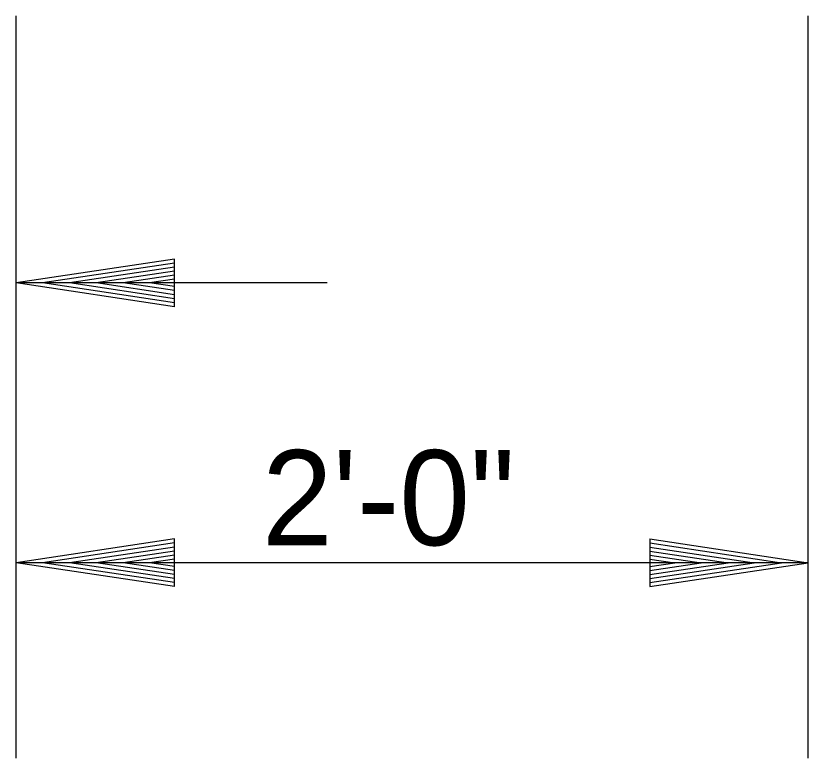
# Model space of a CAD drawing. Extents: x -149 to 1228740, y -106 to 152440.
# Drawn here: x -129.62 to -124.56, y 47.89 to 52.62 of the extents above; entities that cross this region are included whole.
import ezdxf

# ---------------------------------------------------------------- set-up
doc = ezdxf.new("R2010")
doc.units = 0
doc.layers.add('R_Annotation', color=7, linetype='Continuous')
doc.layers.add('R_Dimension', color=7, linetype='Continuous')

msp = doc.modelspace()

# ---------------------------------------------------------------- linework, layer by layer
at = {"layer": 'R_Dimension'}
for p, q in [((-129.6197, 52.6229), (-129.6197, 47.8891)), ((-124.5662, 52.6229), (-124.5662, 47.8891)), ((-128.6075, 51.0711), (-129.6182, 50.9195)), ((-128.6075, 50.7679), (-128.6075, 51.0711)), ((-128.6075, 51.0458), (-129.4489, 50.9195)), ((-128.6075, 51.0205), (-129.2771, 50.9195)), ((-128.6075, 50.9953), (-129.1078, 50.9195)), ((-128.6075, 50.97), (-128.936, 50.9195)), ((-127.6329, 50.9203), (-129.6197, 50.9203)), ((-128.6075, 50.7679), (-129.6182, 50.9195)), ((-128.6075, 50.7931), (-129.4489, 50.9195)), ((-128.6075, 50.8184), (-129.2771, 50.9195)), ((-128.6075, 50.8437), (-129.1078, 50.9195)), ((-128.6075, 50.8715), (-128.936, 50.9195)), ((-128.6075, 50.9447), (-128.7667, 50.9195)), ((-128.6075, 50.8967), (-128.7667, 50.9195)), ((-128.6075, 49.2872), (-129.6182, 49.1356)), ((-128.6075, 48.984), (-128.6075, 49.2872)), ((-125.5755, 49.2872), (-124.5648, 49.1356)), ((-125.5755, 49.2872), (-125.5755, 48.984)), ((-128.6075, 49.2619), (-129.4489, 49.1356)), ((-125.5755, 49.2619), (-124.7341, 49.1356)), ((-128.6075, 49.2342), (-129.2771, 49.1356)), ((-128.6075, 49.2089), (-129.1078, 49.1356)), ((-125.5755, 49.2342), (-124.9084, 49.1356)), ((-125.5755, 49.2089), (-125.0752, 49.1356)), ((-124.5662, 49.1347), (-129.6197, 49.1347)), ((-128.6075, 48.984), (-129.6182, 49.1356)), ((-128.6075, 49.0093), (-129.4489, 49.1356)), ((-128.6075, 49.0345), (-129.2771, 49.1356)), ((-128.6075, 49.0598), (-129.1078, 49.1356)), ((-128.6075, 49.1836), (-128.936, 49.1356)), ((-128.6075, 49.0851), (-128.936, 49.1356)), ((-128.6075, 49.1584), (-128.7667, 49.1356)), ((-128.6075, 49.1103), (-128.7667, 49.1356)), ((-125.5755, 49.1836), (-125.247, 49.1356)), ((-125.5755, 49.1584), (-125.4163, 49.1356)), ((-125.5755, 48.984), (-124.5648, 49.1356)), ((-125.5755, 49.0851), (-125.247, 49.1356)), ((-125.5755, 49.0345), (-124.9084, 49.1356)), ((-125.5755, 49.0093), (-124.7341, 49.1356)), ((-125.5755, 49.0598), (-125.0752, 49.1356)), ((-125.5755, 49.1103), (-125.4163, 49.1356))]:
    msp.add_line(p, q, dxfattribs=at)

# ---------------------------------------------------------------- texts
at = {"layer": 'R_Annotation'}
msp.add_text('2\'-0"', height=0.60645, dxfattribs=at).set_placement((-128.0491, 49.2468))

doc.saveas('drawing.dxf')
